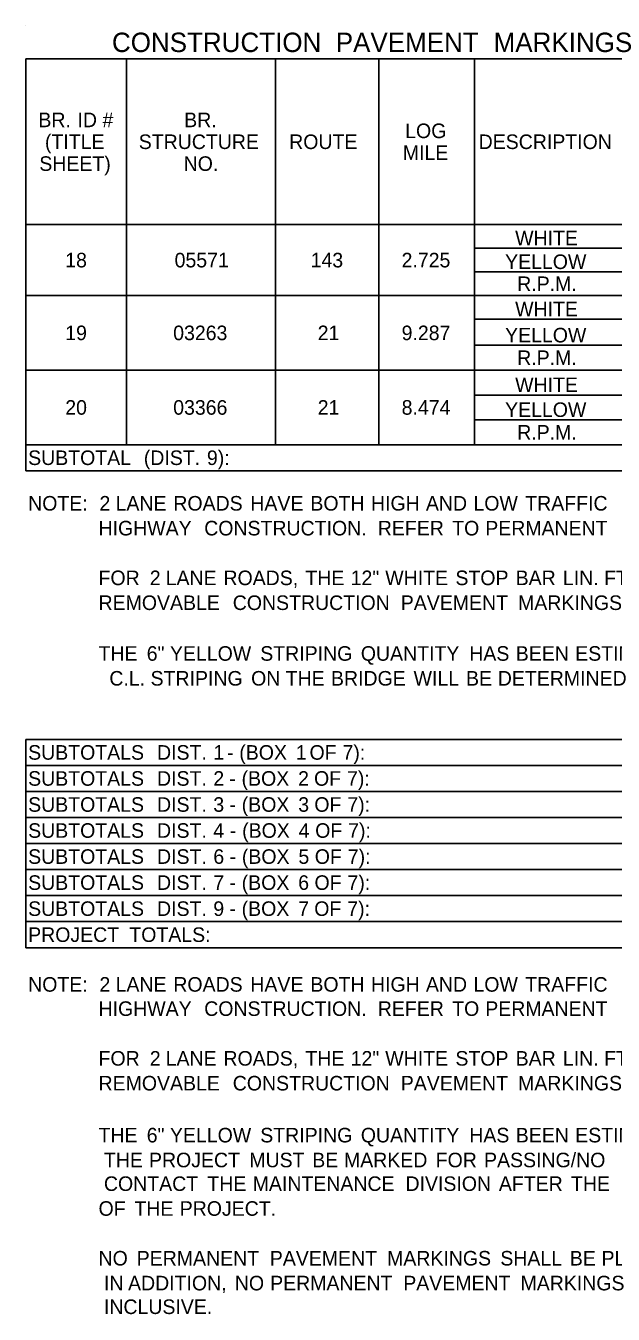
# Model space of a CAD drawing. Extents: x 544255 to 1930787, y -1947044 to 596640.
# Drawn here: x 546531 to 546773, y -1946835 to -1946304 of the extents above; entities that cross this region are included whole.
import ezdxf

# ---------------------------------------------------------------- set-up
doc = ezdxf.new("R2010")
doc.units = 0
doc.layers.add('Default', color=7, linetype='Continuous')

msp = doc.modelspace()

# ---------------------------------------------------------------- linework, layer by layer
at = {"layer": 'Default'}
for p, q in [((546530.88, -1946303.83), (546530.88, -1946303.83)), ((546530.88, -1946317.48), (547165.12, -1946317.48)), ((546530.88, -1946317.48), (546836.06, -1946317.48)), ((546530.88, -1946487.13), (546530.88, -1946317.48)), ((546572.32, -1946476.41), (546572.32, -1946317.48)), ((546633.75, -1946476.41), (546633.75, -1946317.48)), ((546676.16, -1946476.41), (546676.16, -1946317.48)), ((546715.65, -1946476.41), (546715.65, -1946317.48)), ((546530.88, -1946385.73), (546715.65, -1946385.73)), ((546530.88, -1946385.73), (546676.16, -1946385.73)), ((546676.16, -1946385.73), (547165.12, -1946385.73)), ((546715.65, -1946395.48), (547165.12, -1946395.48)), ((546715.65, -1946405.23), (547165.12, -1946405.23)), ((546530.88, -1946414.98), (547165.12, -1946414.98)), ((546715.65, -1946424.73), (547165.12, -1946424.73)), ((546715.65, -1946435.46), (547165.12, -1946435.46)), ((546530.88, -1946445.7), (547165.12, -1946445.7)), ((546715.65, -1946455.93), (547165.12, -1946455.93)), ((546715.65, -1946466.17), (547165.12, -1946466.17)), ((546530.88, -1946476.41), (547165.12, -1946476.41)), ((546530.88, -1946487.13), (547165.12, -1946487.13)), ((546530.88, -1946597.8), (547165.12, -1946597.8)), ((546530.88, -1946597.8), (547165.12, -1946597.8)), ((546530.88, -1946683.6), (546530.88, -1946597.8)), ((546530.88, -1946608.52), (547165.12, -1946608.52)), ((546530.88, -1946619.25), (547165.12, -1946619.25)), ((546530.88, -1946629.97), (547165.12, -1946629.97)), ((546530.88, -1946640.7), (547165.12, -1946640.7)), ((546530.88, -1946651.42), (547165.12, -1946651.42)), ((546530.88, -1946662.15), (547165.12, -1946662.15)), ((546530.88, -1946672.87), (547165.12, -1946672.87)), ((546530.88, -1946683.6), (547165.12, -1946683.6))]:
    msp.add_line(p, q, dxfattribs=at)

# ---------------------------------------------------------------- texts
for s, height, p in [('CONSTRUCTION', 8, (546566.37, -1946314.66)), (' PAVEMENT', 8, (546655.52, -1946314.66)), (' MARKINGS', 8, (546720.51, -1946314.66)), ('BR.', 6, (546536.08, -1946345.61)), (' ID', 6, (546549.94, -1946345.61)), (' #', 6, (546560.23, -1946345.61)), ('BR.', 6, (546596.1, -1946345.61)), ('LOG', 6, (546687.07, -1946350.11)), ('(TITLE', 6, (546538.77, -1946354.61)), ('STRUCTURE', 6, (546577.39, -1946354.61)), ('ROUTE', 6, (546639.32, -1946354.61)), ('DESCRIPTION', 6, (546717.32, -1946354.61)), ('SHEET)', 6, (546536.45, -1946363.61)), ('NO.', 6, (546595.87, -1946363.61)), ('MILE', 6, (546686.1, -1946359.11)), ('WHITE', 6, (546732.35, -1946394.28)), ('18', 6, (546547.13, -1946403.36)), ('05571', 6, (546592.15, -1946403.36)), ('143', 6, (546648.15, -1946403.36)), ('2.725', 6, (546685.59, -1946403.36)), ('YELLOW', 6, (546728.21, -1946404.03)), ('R.P.M.', 6, (546733.19, -1946413.11)), ('WHITE', 6, (546732.35, -1946423.53)), ('19', 6, (546547.13, -1946433.34)), ('03263', 6, (546591.57, -1946433.34)), ('21', 6, (546651.06, -1946433.34)), ('9.287', 6, (546685.61, -1946433.34)), ('YELLOW', 6, (546728.21, -1946434.26)), ('R.P.M.', 6, (546733.19, -1946443.58)), ('WHITE', 6, (546732.35, -1946454.73)), ('20', 6, (546547.14, -1946464.05)), ('03366', 6, (546591.57, -1946464.05)), ('21', 6, (546651.06, -1946464.05)), ('8.474', 6, (546685.62, -1946464.05)), ('YELLOW', 6, (546728.21, -1946464.97)), ('R.P.M.', 6, (546733.19, -1946474.29)), ('SUBTOTAL', 6, (546531.86, -1946484.77)), (' (DIST.', 6, (546577.25, -1946484.77)), (' 9):', 6, (546603.22, -1946484.77)), ('NOTE:', 6, (546531.86, -1946503.54)), ('  2', 6, (546556.75, -1946503.54)), (' LANE', 6, (546565.62, -1946503.54)), (' ROADS', 6, (546589.4, -1946503.54)), (' HAVE', 6, (546621.1, -1946503.54)), (' BOTH', 6, (546645.82, -1946503.54)), (' HIGH', 6, (546670.76, -1946503.54)), (' AND', 6, (546693.37, -1946503.54)), (' LOW', 6, (546712.95, -1946503.54)), (' TRAFFIC', 6, (546734.28, -1946503.54)), ('             HIGHWAY', 6, (546531.86, -1946513.78)), (' CONSTRUCTION.', 6, (546602.11, -1946513.78)), (' REFER', 6, (546673.57, -1946513.78)), (' TO', 6, (546704.2, -1946513.78)), (' PERMANENT', 6, (546717.8, -1946513.78)), ('             FOR', 6, (546531.86, -1946534.25)), (' 2', 6, (546579.7, -1946534.25)), (' LANE', 6, (546586.25, -1946534.25)), (' ROADS,', 6, (546610.03, -1946534.25)), (' THE', 6, (546643.76, -1946534.25)), (' 12"', 6, (546662.4, -1946534.25)), (' WHITE', 6, (546676.64, -1946534.25)), (' STOP', 6, (546705.53, -1946534.25)), (' BAR', 6, (546730.32, -1946534.25)), (' LIN.', 6, (546749.77, -1946534.25)), (' FT.', 6, (546766.74, -1946534.25)), ('             REMOVABLE', 6, (546531.86, -1946544.49)), (' CONSTRUCTION', 6, (546613.86, -1946544.49)), (' PAVEMENT', 6, (546683.03, -1946544.49)), (' MARKINGS', 6, (546731.32, -1946544.49)), ('             THE', 6, (546531.86, -1946565.4)), (' 6"', 6, (546578.44, -1946565.4)), (' YELLOW', 6, (546588.01, -1946565.4)), (' STRIPING', 6, (546625.18, -1946565.4)), (' QUANTITY', 6, (546666.58, -1946565.4)), (' HAS', 6, (546711.23, -1946565.4)), (' BEEN', 6, (546730.36, -1946565.4)), (' ESTIMATED', 6, (546754.84, -1946565.4)), (' C.L.', 6, (546563.06, -1946575.63)), (' STRIPING', 6, (546580.03, -1946575.63)), (' ON', 6, (546621.42, -1946575.63)), (' THE', 6, (546635.64, -1946575.63)), (' BRIDGE', 6, (546654.29, -1946575.63)), (' WILL', 6, (546688.31, -1946575.63)), (' BE', 6, (546709.9, -1946575.63)), (' DETERMINED', 6, (546722.97, -1946575.63)), ('SUBTOTALS', 6, (546531.86, -1946606.16)), (' DIST.', 6, (546582.69, -1946606.16)), (' 1', 6, (546605.86, -1946606.16)), (' (BOX', 6, (546616.55, -1946606.16)), (' 1', 6, (546639.83, -1946606.16)), (' OF', 6, (546645.46, -1946606.16)), (' 7):', 6, (546659.04, -1946606.16)), (' -', 6, (546611.49, -1946606.16)), ('SUBTOTALS', 6, (546531.86, -1946616.88)), (' DIST.', 6, (546582.69, -1946616.88)), (' 2', 6, (546605.86, -1946616.88)), (' (BOX', 6, (546617.49, -1946616.88)), (' 2', 6, (546640.76, -1946616.88)), (' OF', 6, (546647.33, -1946616.88)), (' 7):', 6, (546660.91, -1946616.88)), (' -', 6, (546612.43, -1946616.88)), ('SUBTOTALS', 6, (546531.86, -1946627.61)), (' DIST.', 6, (546582.69, -1946627.61)), (' 3', 6, (546605.86, -1946627.61)), (' (BOX', 6, (546617.55, -1946627.61)), (' 3', 6, (546640.82, -1946627.61)), (' OF', 6, (546647.45, -1946627.61)), (' 7):', 6, (546661.03, -1946627.61)), (' -', 6, (546612.49, -1946627.61)), ('SUBTOTALS', 6, (546531.86, -1946638.33)), (' DIST.', 6, (546582.69, -1946638.33)), (' 4', 6, (546605.86, -1946638.33)), (' (BOX', 6, (546617.72, -1946638.33)), (' 4', 6, (546640.99, -1946638.33)), (' OF', 6, (546647.79, -1946638.33)), (' 7):', 6, (546661.37, -1946638.33)), (' -', 6, (546612.66, -1946638.33)), ('SUBTOTALS', 6, (546531.86, -1946649.06)), (' DIST.', 6, (546582.69, -1946649.06)), (' 6', 6, (546605.86, -1946649.06)), (' (BOX', 6, (546617.61, -1946649.06)), (' 5', 6, (546640.89, -1946649.06)), (' OF', 6, (546647.62, -1946649.06)), (' 7):', 6, (546661.21, -1946649.06)), (' -', 6, (546612.55, -1946649.06)), ('SUBTOTALS', 6, (546531.86, -1946659.78)), (' DIST.', 6, (546582.69, -1946659.78)), (' 7', 6, (546605.86, -1946659.78)), (' (BOX', 6, (546617.54, -1946659.78)), (' 6', 6, (546640.81, -1946659.78)), (' OF', 6, (546647.51, -1946659.78)), (' 7):', 6, (546661.09, -1946659.78)), (' -', 6, (546612.48, -1946659.78)), ('SUBTOTALS', 6, (546531.86, -1946670.51)), (' DIST.', 6, (546582.69, -1946670.51)), (' 9', 6, (546605.86, -1946670.51)), (' (BOX', 6, (546617.52, -1946670.51)), (' 7', 6, (546640.8, -1946670.51)), (' OF', 6, (546647.41, -1946670.51)), (' 7):', 6, (546661, -1946670.51)), (' -', 6, (546612.46, -1946670.51)), ('PROJECT', 6, (546531.86, -1946681.23)), (' TOTALS:', 6, (546571.28, -1946681.23)), ('NOTE:', 6, (546531.86, -1946701.71)), ('  2', 6, (546556.75, -1946701.71)), (' LANE', 6, (546565.62, -1946701.71)), (' ROADS', 6, (546589.4, -1946701.71)), (' HAVE', 6, (546621.1, -1946701.71)), (' BOTH', 6, (546645.82, -1946701.71)), (' HIGH', 6, (546670.76, -1946701.71)), (' AND', 6, (546693.37, -1946701.71)), (' LOW', 6, (546712.95, -1946701.71)), (' TRAFFIC', 6, (546734.28, -1946701.71)), ('             HIGHWAY', 6, (546531.86, -1946711.7)), (' CONSTRUCTION.', 6, (546602.11, -1946711.7)), (' REFER', 6, (546673.57, -1946711.7)), (' TO', 6, (546704.2, -1946711.7)), (' PERMANENT', 6, (546717.8, -1946711.7)), ('             FOR', 6, (546531.86, -1946732.18)), (' 2', 6, (546579.7, -1946732.18)), (' LANE', 6, (546586.25, -1946732.18)), (' ROADS,', 6, (546610.03, -1946732.18)), (' THE', 6, (546643.76, -1946732.18)), (' 12"', 6, (546662.4, -1946732.18)), (' WHITE', 6, (546676.64, -1946732.18)), (' STOP', 6, (546705.53, -1946732.18)), (' BAR', 6, (546730.32, -1946732.18)), (' LIN.', 6, (546749.77, -1946732.18)), (' FT.', 6, (546766.74, -1946732.18)), ('             REMOVABLE', 6, (546531.86, -1946742.41)), (' CONSTRUCTION', 6, (546613.86, -1946742.41)), (' PAVEMENT', 6, (546683.03, -1946742.41)), (' MARKINGS', 6, (546731.32, -1946742.41)), ('             THE', 6, (546531.86, -1946763.81)), (' 6"', 6, (546578.44, -1946763.81)), (' YELLOW', 6, (546588.01, -1946763.81)), (' STRIPING', 6, (546625.18, -1946763.81)), (' QUANTITY', 6, (546666.58, -1946763.81)), (' HAS', 6, (546711.23, -1946763.81)), (' BEEN', 6, (546730.36, -1946763.81)), (' ESTIMATED', 6, (546754.84, -1946763.81)), ('THE', 6, (546563.06, -1946774.05)), (' PROJECT', 6, (546579.38, -1946774.05)), (' MUST', 6, (546620.67, -1946774.05)), (' BE', 6, (546646.58, -1946774.05)), (' MARKED', 6, (546659.65, -1946774.05)), (' FOR', 6, (546697.4, -1946774.05)), (' PASSING/NO', 6, (546717.31, -1946774.05)), ('CONTACT', 6, (546563.06, -1946783.8)), (' THE', 6, (546603.41, -1946783.8)), (' MAINTENANCE', 6, (546622.06, -1946783.8)), (' DIVISION', 6, (546684.97, -1946783.8)), (' AFTER', 6, (546723.41, -1946783.8)), (' THE', 6, (546753.11, -1946783.8)), ('             OF', 6, (546531.86, -1946794.03)), (' THE', 6, (546573.38, -1946794.03)), (' PROJECT.', 6, (546592.03, -1946794.03)), ('             NO', 6, (546531.86, -1946814.51)), (' PERMANENT', 6, (546574.32, -1946814.51)), (' PAVEMENT', 6, (546629.12, -1946814.51)), (' MARKINGS', 6, (546677.4, -1946814.51)), (' SHALL', 6, (546724.01, -1946814.51)), (' BE', 6, (546752.61, -1946814.51)), (' PLACED', 6, (546765.67, -1946814.51)), ('IN', 6, (546563.06, -1946824.75)), (' ADDITION,', 6, (546570.76, -1946824.75)), (' NO', 6, (546614.72, -1946824.75)), (' PERMANENT', 6, (546629.25, -1946824.75)), (' PAVEMENT', 6, (546684.05, -1946824.75)), (' MARKINGS', 6, (546732.33, -1946824.75)), ('INCLUSIVE.', 6, (546563.06, -1946834.5))]:
    msp.add_text(s, height=height, dxfattribs=at).set_placement(p)

doc.saveas('drawing.dxf')
